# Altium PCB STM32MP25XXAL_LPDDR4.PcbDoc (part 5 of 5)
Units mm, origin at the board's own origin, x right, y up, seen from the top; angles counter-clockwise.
Board outline 125 x 95 mm, 6 copper layers (Top Layer, Signal Layer 1, Signal Layer 2, Signal Layer 3, Signal Layer 4, Bottom Layer), stack 1.403 mm thick; 182 components, 297 nets, 1131 pads, 958 vias.
Unrouted connection lines stored in the file: 5.
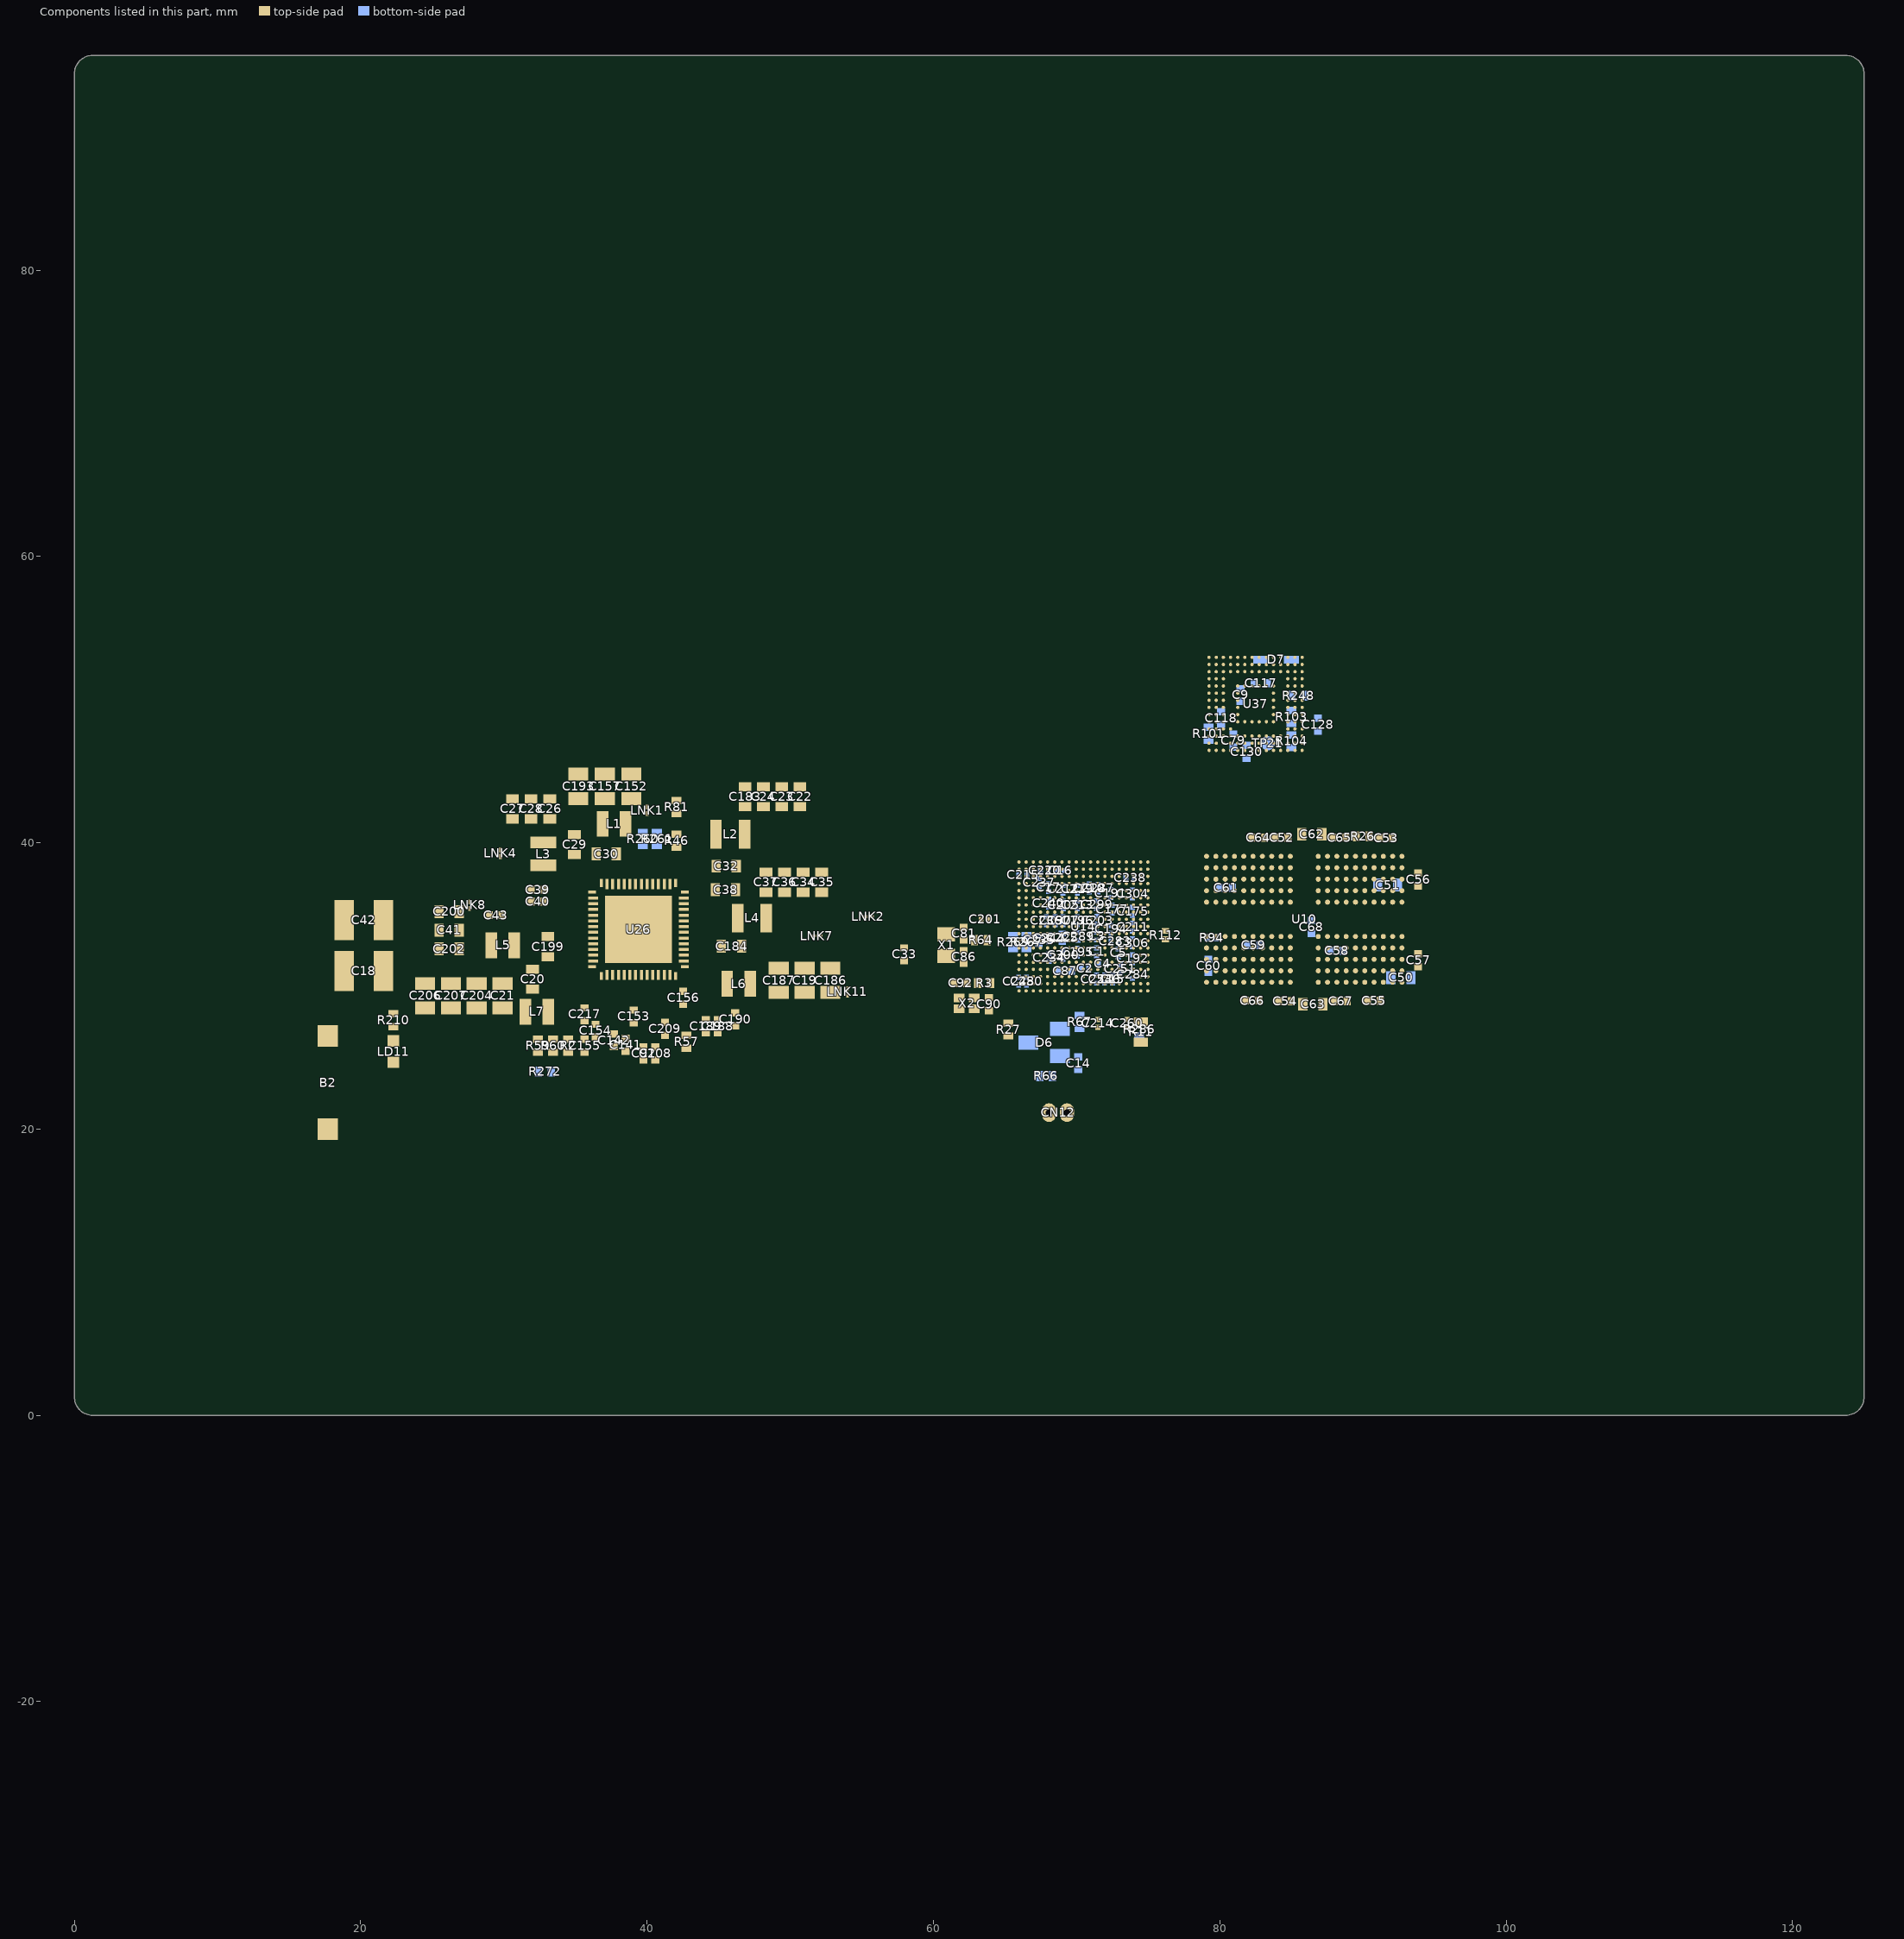
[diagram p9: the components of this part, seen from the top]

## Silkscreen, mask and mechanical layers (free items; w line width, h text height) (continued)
Drill Drawing:
  drawing of 411 lines, arcs and shapes, not listed
  text "MINIMUN PARAMETERS" at 150.3,143.65 h1.2
  text "PCB SPECIFICATIONS :" at -1.425,142.95 h1.2
  text "A.   MATERIAL :" at -1.425,138.95 h1.2
  text "FR-4" at 37.075,138.95 h1.2
  text "TG-170" at 53.575,138.95 h1.2
  text "X  TG-150" at 71.825,138.95 h1.2
  text "TG-140" at 87.825,138.95 h1.2
  text "DEFAULT" at 150.3,138.15 h1.2
  text "B.   MATERIAL FAMILY :" at -1.425,135.95 h1.2
  text "N/A" at 37.075,135.95 h1.2
  text "C.   SOLDERMASK COLOR :" at -1.425,132.95 h1.2
  text "GREEN" at 37.075,132.95 h1.2
  text "X  BLUE" at 53.575,132.95 h1.2
  text "RED" at 71.825,132.95 h1.2
  text "BLACK" at 87.825,132.95 h1.2
  text "TRACKS : 0.100mm           / GAPS : 0.100mm" at 150.3,132.4 h1.2
  text "D.   SILKSCREEN COLOR :" at -1.425,129.95 h1.2
  text "X  WHITE" at 37.075,129.95 h1.2
  text "YELLOW" at 53.575,129.95 h1.2
  text "BLACK" at 71.825,129.95 h1.2
  text "E.   SURFACE FINISH :" at -1.425,126.95 h1.2
  text "X  ENIG" at 37.075,126.95 h1.2
  text "IMMERSION SILVER" at 53.575,126.95 h1.2
  text "IMMERSION TIN" at 87.825,126.95 h1.2
  text "UNDER MPU" at 150.3,125.9 h1.2
  text "HASL" at 37.075,123.95 h1.2
  text "HASL (PB-FREE)" at 53.575,123.95 h1.2
  text "GOLDEN FINGER" at 87.825,123.95 h1.2
  text "F.   IMPEDANCE CONTROL :" at -1.425,120.95 h1.2
  text "NO" at 37.075,120.95 h1.2
  text "X  YES  (SEE IMPEDANCE TABLE FOR DETAIL INFORMATION)" at 53.575,120.95 h1.2
  text "TRACKS : 0.075mm           / GAPS : 0.082mm" at 150.3,120.15 h1.2
  text "G.   THROUGH VIA :" at -1.425,117.95 h1.2
  text "PLUG THE VIAS WHICH ARE COVERED WITH SOLDERMASK ONE OR TWO SIDE." at 37.075,117.95 h1.2
  text "PLUG MATERIAL :" at 37.075,114.95 h1.2
  text "X  SOLDERMASK" at 62.575,114.95 h1.2
  text "NON-CONDUCTIVE EPOXY." at 87.825,114.95 h1.2
  text "UNDER DDR" at 150.3,113.9 h1.2
  text "H.   STACK-UP :" at -1.425,111.95 h1.2
  text "SEE LAYER STACK-UP SEQUENCE FOR OVERALL THICKNESS." at 37.075,111.95 h1.2
  text "TRACKS : 0.090mm           / GAPS : 0.090mm" at 150.3,108.15 h1.2
  text "Layer" at 135.6,101.625 h2
  text "Name" at 143.974,101.625 h2
  text "Material" at 160.171,101.625 h2
  text "Thickness" at 174.725,101.625 h2
  text "Constant" at 186.68,101.625 h2
  text "Board Layer Stack" at 197.744,101.625 h2
  text "Top Overlay" at 143.974,97.625 h2
  text "Top Solder" at 143.974,93.625 h2
  text "Solder Resist" at 160.171,93.625 h2
  text "0.025mm" at 174.725,93.625 h2
  text "3.5" at 186.68,93.625 h2
  text "1" at 135.6,89.625 h2
  text "Top Layer" at 143.974,89.625 h2
  text "0.046mm" at 174.725,89.625 h2
  text "Dielectric 1" at 143.974,85.625 h2
  text "0.071mm" at 174.725,85.625 h2
  text "4.21" at 186.68,85.625 h2
  text "2" at 135.598,81.625 h2
  text "Signal Layer 1" at 143.974,81.625 h2
  text "0.035mm" at 174.725,81.625 h2
  text "Dielectric 2" at 143.974,77.625 h2
  text "0.094mm" at 174.725,77.625 h2
  text "4.09" at 186.68,77.625 h2
  text "3" at 135.6,73.625 h2
  text "Signal Layer 2" at 143.974,73.625 h2
  text "0.023mm" at 174.725,73.625 h2
  text "Dielectric 3" at 143.974,69.625 h2
  text "0.865mm" at 174.725,69.625 h2
  text "4.68" at 186.68,69.625 h2
  text "4" at 135.6,65.625 h2
  text "Signal Layer 3" at 143.974,65.625 h2
  text "0.023mm" at 174.725,65.625 h2
  text "Dielectric 4" at 143.974,61.625 h2
  text "0.094mm" at 174.725,61.625 h2
  text "4.09" at 186.68,61.625 h2
  text "5" at 135.6,57.625 h2
  text "Signal Layer 4" at 143.974,57.625 h2
  text "0.035mm" at 174.725,57.625 h2
  text "Dielectric5" at 143.974,53.625 h2
  text "0.071mm" at 174.725,53.625 h2
  text "4.21" at 186.68,53.625 h2
  text "6" at 135.6,49.625 h2
  text "Bottom Layer" at 143.974,49.625 h2
  text "0.046mm" at 174.725,49.625 h2
  text "Bottom Solder" at 143.974,45.625 h2
  text "Solder Resist" at 160.171,45.625 h2
  text "0.025mm" at 174.725,45.625 h2
  text "3.5" at 186.68,45.625 h2
  text "Bottom Overlay" at 143.974,41.625 h2
  text "Symbol" at 136.02,-10.957 h2.4
  text "Count" at 145.419,-10.957 h2.4
  text "Hole Size" at 155.174,-10.957 h2.4
  text "Plated" at 173.451,-10.957 h2.4
  text "Hole Type" at 181.702,-10.957 h2.4
  text "Drill Layer Pair" at 193.714,-10.957 h2.4
  text "Via/Pad" at 216.494,-10.957 h2.4
  text "Pad Shape" at 226.337,-10.957 h2.4
  text "Template" at 239.194,-10.957 h2.4
  text "Hole Tolerance (+)" at 270.377,-10.957 h2.4
  text "Hole Tolerance (-)" at 290.456,-10.957 h2.4
  text "2" at 145.419,-15.1 h2
  text "0.500mm (19.69mil)" at 155.174,-15.1 h2
  text "PTH" at 173.451,-15.1 h2
  text "Round" at 181.702,-15.1 h2
  text "Top Layer - Bottom Layer" at 193.714,-15.1 h2
  text "Pad" at 216.494,-15.1 h2
  text "Rounded" at 226.337,-15.1 h2
  text "r100_130h50r100m105_135(Tol5-5)" at 239.194,-15.1 h2
  text "0.050mm (1.97mil)" at 270.377,-15.1 h2
  text "0.050mm (1.97mil)" at 290.456,-15.1 h2
  text "7" at 145.419,-19.243 h2
  text "0.300mm (11.81mil)" at 155.174,-19.243 h2
  text "PTH" at 173.451,-19.243 h2
  text "Round" at 181.702,-19.243 h2
  text "Top Layer - Bottom Layer" at 193.714,-19.243 h2
  text "Via" at 216.494,-19.243 h2
  text "Rounded" at 226.337,-19.243 h2
  text "v55h30m35" at 239.194,-19.243 h2
  text "55" at 145.419,-23.386 h2
  text "0.350mm (13.78mil)" at 155.174,-23.386 h2
  text "PTH" at 173.451,-23.386 h2
  text "Round" at 181.702,-23.386 h2
  text "Top Layer - Bottom Layer" at 193.714,-23.386 h2
  text "Via" at 216.494,-23.386 h2
  text "Rounded" at 226.337,-23.386 h2
  text "v55h35m40mx40" at 239.194,-23.386 h2
  text "410" at 145.419,-27.529 h2
  text "0.200mm (7.87mil)" at 155.174,-27.529 h2
  text "PTH" at 173.451,-27.529 h2
  text "Round" at 181.702,-27.529 h2
  text "(Mixed)" at 193.714,-27.529 h2
  text "Via" at 216.494,-27.529 h2
  text "Rounded" at 226.337,-27.529 h2
  text "(Mixed)" at 239.194,-27.529 h2
  text "486" at 145.419,-31.672 h2
  text "0.100mm (3.94mil)" at 155.174,-31.672 h2
  text "PTH" at 173.451,-31.672 h2
  text "Round" at 181.702,-31.672 h2
  text "(Mixed)" at 193.714,-31.672 h2
  text "Via" at 216.494,-31.672 h2
  text "Rounded" at 226.337,-31.672 h2
  text "v26h10" at 239.194,-31.672 h2
  text "960 Total" at 145.419,-35.815 h2
M20-Top Sheet Box:
  circle w0.254: c105.427,-32.893 r1.3
  region: 90.949,-33.986 80.193,-33.986 81.186,-31.493 89.044,-31.493 89.493,-30.734 91.701,-33.282
  region: 104.952,-25.657 89.425,-25.657 88.731,-27.432 87.52,-28.657 86.123,-26.797 86.123,-25.146 87.266,-23.749 88.702,-23.371 104.952,-23.371
  lines w0.254: 81.186,-31.493 89.978,-31.493 86.912,-27.956 cw(c88.716,-26.012) 88.956,-23.371 105.72,-23.371 104.958,-25.657 ; 84.5,-23.124 cw(c86.926,-24.094) 87.163,-21.492 ; 84.539,-23.091 80.193,-33.986 99.515,-33.986 ccw(c99.764,-31.252) 102.313,-32.272 ; 86.279,-27.026 91.701,-33.282 ; 86.533,-27.026 91.838,-33.147 ; 86.533,-26.772 91.838,-32.893 ; 86.631,-25.657 99.624,-25.657 ; 86.66,-26.645 91.965,-32.766 ; 86.787,-26.518 92.092,-32.639 ; 86.914,-26.391 92.219,-32.512 ; 87.041,-26.264 92.346,-32.385 ; 87.096,-24.312 92.401,-30.433 ; 87.164,-21.492 106.614,-21.492 102.314,-32.269 ; 87.168,-26.137 92.418,-32.195 ; 87.168,-25.883 92.473,-32.004 ; 87.168,-25.629 92.473,-31.75 ; 87.168,-24.74 92.473,-30.861 ; 87.295,-25.502 92.6,-31.623 ; 87.295,-25.121 92.6,-31.242 ; 88.667,-31.507 ccw(c88.772,-30.972) 89.069,-30.515 ; 89.753,-25.643 ccw(c89.727,-26.211) 89.397,-26.673 91.762,-29.401 cw(c89.958,-31.345) 90.691,-33.894 ; 96.034,-33.782 98.924,-25.403 ; 96.257,-33.732 99.126,-25.412 ; 96.384,-33.732 99.253,-25.412 ; 96.638,-33.732 99.507,-25.412 ; 96.892,-33.732 99.761,-25.412 ; 97.146,-33.732 100.015,-25.412 ; 97.4,-33.732 100.269,-25.412 ; 97.654,-33.732 100.523,-25.412 ; 97.908,-33.732 100.777,-25.412 ; 98.162,-33.732 101.031,-25.412 ; 98.37,-33.782 101.26,-25.403 ; 101.26,-25.657 104.952,-25.657 ; 104.284,-25.654 105.046,-23.368 ; 104.45,-25.657 105.212,-23.371 ; 104.704,-25.657 105.466,-23.371
  lines w0.3: 18.423,-32.872 78.423,-32.872 ; 18.423,-27.872 78.423,-27.872 ; 18.423,-22.872 78.423,-22.872 ; 58.423,-37.872 58.423,-22.872 ; 78.423,-37.872 78.423,-17.872 ; 96.034,-33.782 98.37,-33.782 ; 18.423,-37.872 108.423,-37.872 108.423,-17.872 18.423,-17.872 18.423,-37.872
M21-Bottom Sheet Box:
  circle w0.254: c21.598,-32.885 r1.3
  region: 22.073,-25.649 37.6,-25.649 38.295,-27.424 39.505,-28.649 40.902,-26.789 40.902,-25.138 39.759,-23.741 38.323,-23.363 22.073,-23.363
  region: 36.076,-33.978 46.832,-33.978 45.839,-31.485 37.981,-31.485 37.533,-30.726 35.324,-33.274
  lines w0.254: 21.559,-23.363 22.321,-25.649 ; 21.813,-23.363 22.575,-25.649 ; 21.979,-23.36 22.741,-25.646 ; 22.067,-25.649 21.305,-23.363 38.069,-23.363 cw(c38.309,-26.004) 40.113,-27.948 37.047,-31.485 45.839,-31.485 ; 22.073,-25.649 25.766,-25.649 ; 24.711,-32.261 20.412,-21.484 39.861,-21.484 ; 24.712,-32.264 ccw(c27.261,-31.244) 27.51,-33.978 46.832,-33.978 42.486,-23.083 ; 25.766,-25.395 28.655,-33.774 ; 25.994,-25.404 28.863,-33.724 ; 26.248,-25.404 29.117,-33.724 ; 26.502,-25.404 29.371,-33.724 ; 26.756,-25.404 29.625,-33.724 ; 27.01,-25.404 29.879,-33.724 ; 27.264,-25.404 30.133,-33.724 ; 27.401,-25.649 40.394,-25.649 ; 27.518,-25.404 30.387,-33.724 ; 27.772,-25.404 30.641,-33.724 ; 27.899,-25.404 30.768,-33.724 ; 28.101,-25.395 30.991,-33.774 ; 34.425,-31.615 39.73,-25.494 ; 34.425,-31.234 39.73,-25.113 ; 34.552,-31.996 39.857,-25.875 ; 34.552,-31.742 39.857,-25.621 ; 34.552,-30.853 39.857,-24.732 ; 34.607,-32.187 39.857,-26.129 ; 34.625,-30.425 39.93,-24.304 ; 34.679,-32.377 39.984,-26.256 ; 34.806,-32.504 40.111,-26.383 ; 34.933,-32.631 40.238,-26.51 ; 35.06,-32.758 40.365,-26.637 ; 35.187,-33.139 40.492,-27.018 ; 35.187,-32.885 40.492,-26.764 ; 35.324,-33.274 40.746,-27.018 ; 36.335,-33.886 cw(c37.067,-31.337) 35.264,-29.394 37.628,-26.665 ccw(c37.298,-26.203) 37.272,-25.635 ; 37.956,-30.507 ccw(c38.254,-30.964) 38.359,-31.499 ; 39.863,-21.484 cw(c40.099,-24.086) 42.525,-23.116
  lines w0.3: 28.655,-33.774 30.991,-33.774 ; 48.416,-37.864 48.416,-17.864 ; 48.416,-32.864 108.416,-32.864 ; 48.416,-27.864 108.416,-27.864 ; 48.416,-22.864 108.416,-22.864 ; 68.416,-37.864 68.416,-22.864 ; 18.416,-37.864 18.416,-17.864 108.416,-17.864 108.416,-37.864 18.416,-37.864

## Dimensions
1.27,0 to 1.27,95 on M2-Board Dimensions
0,93.73 to 125,93.73 on M2-Board Dimensions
